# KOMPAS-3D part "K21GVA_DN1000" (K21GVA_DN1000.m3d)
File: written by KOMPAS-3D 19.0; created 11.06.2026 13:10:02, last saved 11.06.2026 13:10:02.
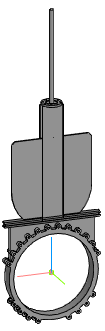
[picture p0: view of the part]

Document properties: Автор: Энергия; Полное имя файла: Z:\3.Личные\kachalov\001_3d для проектировщиков\2.5 Тип_K21GVA. Задвижка\_stp\_stp_K21GVA_DN50-DN1000_с фланцем\K21GVA_DN1000.m3d

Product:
- Part/product: K21GVA_DN1000

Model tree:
1. Операция без истории:1  (labels: K21GVA_DN1000)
